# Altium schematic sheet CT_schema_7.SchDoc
size 218 x 198 mm
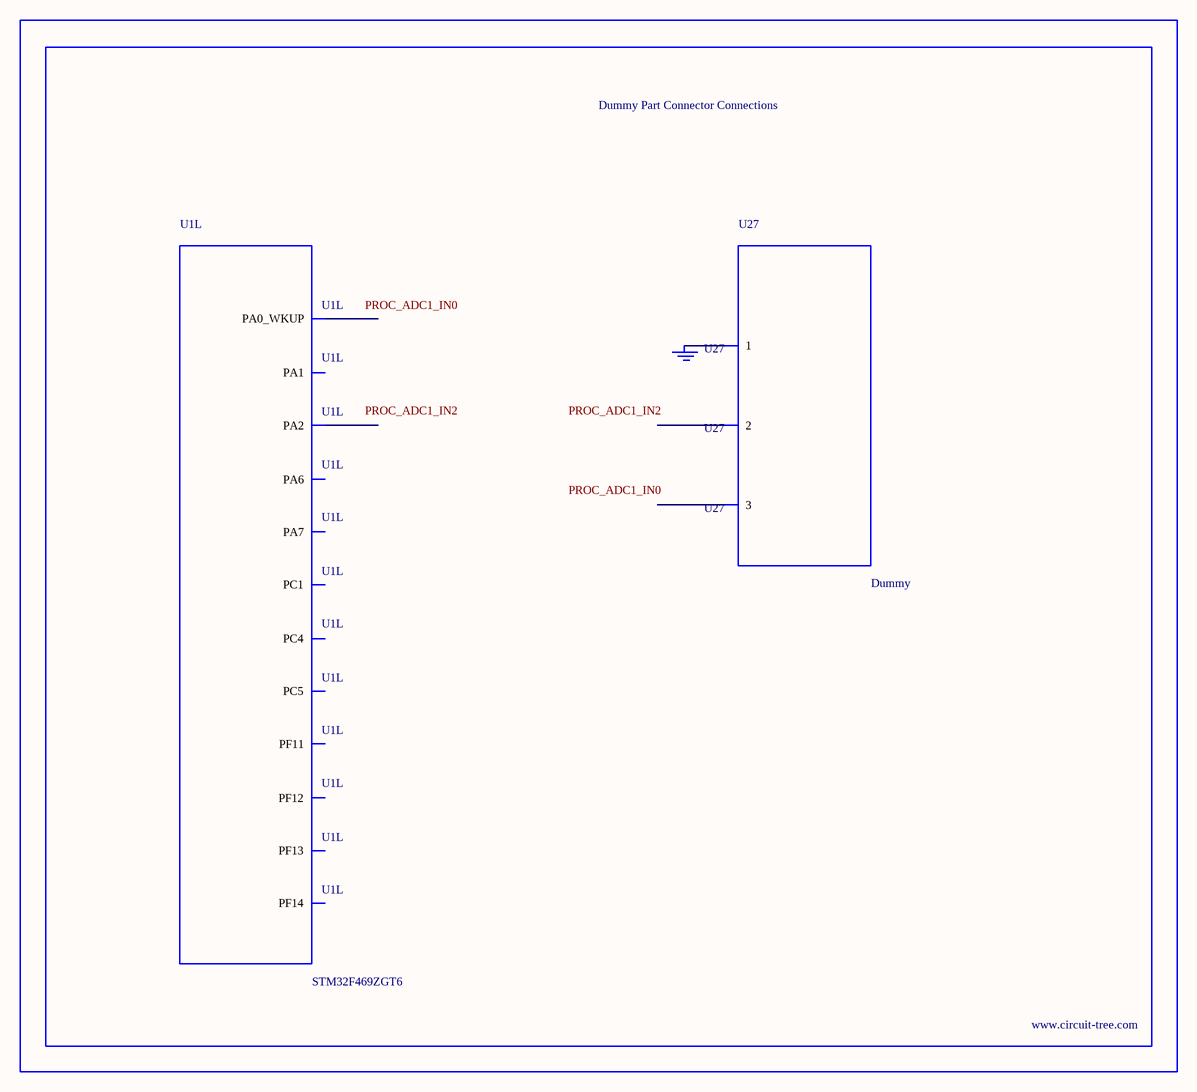
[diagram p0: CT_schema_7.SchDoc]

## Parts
BORDER6  (no value)
GND_INSTANCE_6_0  (no value)
U1  STM32F469ZGT6  [LQFP144]  (part L of 12)
U27  Dummy  [DUMMY_PACKAGE_331]

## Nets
NetGND_INSTANCE_6_0_0: GND_INSTANCE_6_0.0(GND) U27.1

Not connected (* = marked no-connect by the designer): U1 22(PC1) 29(PA0_WKUP) 30(PA1) 31(PA2) 37(PA6) 38(PA7) 39(PC4) 40(PC5) 44(PF11) 45(PF12) 47(PF13) 48(PF14); U27 2 3

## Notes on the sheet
- Labels drawn without touching a wire or pin: PROC_ADC1_IN0, PROC_ADC1_IN2

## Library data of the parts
BORDER6 = BORDER_PAGE6
GND_INSTANCE_6_0 = GND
